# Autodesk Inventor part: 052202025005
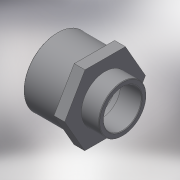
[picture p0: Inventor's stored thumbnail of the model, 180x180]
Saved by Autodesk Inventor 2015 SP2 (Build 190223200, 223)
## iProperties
Created: 2017-10
Part Number: 052202025005
Material: Generic
Description: PLASSON BUSHING ADAP. THR-CEM 25(32)-1/2"
Document SubType Name: Modeling
Designer: KIM
Density: 1 g/cm^3
Appearance: Default
Author: KIM
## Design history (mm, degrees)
derived "052202.ipt"
feature "Solid1::052202.ipt"
tag "TaggingFeature1"
body "Solid1"
other parameters: "d2" = 36, "d13" = 0, "d14" = 0.25, "d17" = 22, "d18" = 19.2, "d19" = 32, "d20" = 25, "d21" = 20.955, "d22" = 19, "d23" = 23.75, "d24" = 16.764, "d25" = 16, "d26" = -22, "d_" = 25, "R_" = 20.955, "C_" = 36, "B_" = 12, "L_" = 22, "lt_" = 16, "D_" = 32, "l_" = 19
